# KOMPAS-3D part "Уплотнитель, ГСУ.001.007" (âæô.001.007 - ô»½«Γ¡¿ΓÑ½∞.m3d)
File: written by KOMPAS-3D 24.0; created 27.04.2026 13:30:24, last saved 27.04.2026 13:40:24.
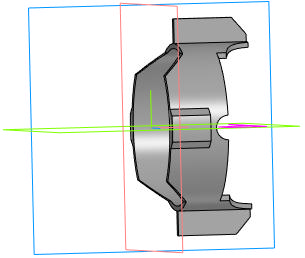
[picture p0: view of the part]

Document properties: Автор: User7; Полное имя файла: C:\Users\User7\Desktop\олимп\ГСУ.001.007 - Уплотнитель.m3d

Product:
- Part/product: Уплотнитель  | designation ГСУ.001.007
    Масса: 0.010592

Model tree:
1. Эскиз:1
2. Элемент выдавливания:1
     Расстояние 1 = 20
3. Эскиз:3  (with: Ребро.Элемент выдавливания:1, Грань.Элемент выдавливания:1)
4. Элемент выдавливания:4
     Расстояние 1 = 17
5. Зеркальный массив:1
6. Экземпляр ( 1 )
7. Экземпляр ( 2 )  (with: Элемент выдавливания:4)
8. Эскиз:2  (with: Ребро.Элемент выдавливания:1)
9. Элемент выдавливания:2
     Расстояние 1 = 1
10. Элемент выдавливания:3
     Расстояние 1 = 17
11. Эскиз:4  (with: Грань.Элемент выдавливания:1, Ребро.Элемент выдавливания:1)
12. Элемент выдавливания:5
     Расстояние 2 = 8
13. Массив по концентрической сетке:1  (with: Элемент выдавливания:5, Эскиз:4, Элемент выдавливания:3, Эскиз:2, Элемент выдавливания:2, Зеркальный массив:1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)  (4 pattern instances)
     Шаг 2 = 360

Expressions: 21.4/2; 37/2
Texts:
  ГСУ.001.007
